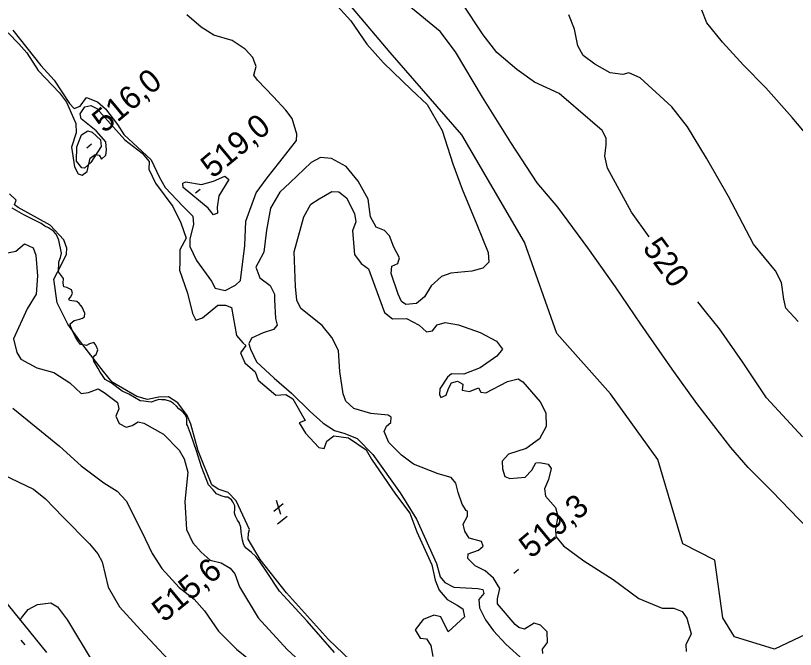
# Model space of a CAD drawing. Extents: x 347059 to 352153, y 6073752 to 6078601.
# Drawn here: x 350645.1 to 350797.1, y 6076601.8 to 6076725.3 of the extents above; entities that cross this region are included whole.
import ezdxf

# ---------------------------------------------------------------- set-up
doc = ezdxf.new("R2010")
doc.units = 0
for name, color, linetype in [('Level 1', 7, 'Continuous'), ('Level 2', 7, 'Continuous'), ('Level 21', 7, 'Continuous'), ('Level 3', 7, 'Continuous'), ('Level 4', 7, 'Continuous'), ('Level 44', 7, 'Continuous')]:
    doc.layers.add(name, color=color, linetype=linetype)

msp = doc.modelspace()

# ---------------------------------------------------------------- linework, layer by layer
at = {"layer": 'Level 1'}
for points in [[(350768.63, 6076682.21), (350765.17, 6076686.97), (350760.48, 6076695.58), (350759.98, 6076697.93), (350760.27, 6076700.13), (350760.25, 6076701.43), (350759.45, 6076702.88), (350757.14, 6076704.91), (350751.05, 6076710.13), (350746.24, 6076712.34), (350742.81, 6076714.77), (350738.91, 6076718.11), (350736.22, 6076721.55), (350732.03, 6076727.94)], [(350798.53, 6076643.18), (350791.52, 6076650.79), (350786.82, 6076657.81), (350782.34, 6076664.23), (350779.58, 6076667.6), (350778.1, 6076669.52)], [(350644.55, 6076648.8), (350653.61, 6076641.41), (350657.83, 6076637.53), (350662.25, 6076634.21), (350664.89, 6076632.58), (350666.66, 6076630.74), (350669.66, 6076624.68), (350671.7, 6076620.44), (350673.57, 6076617.51), (350676.95, 6076613.86), (350679.89, 6076611.55), (350681.9, 6076609.26)], [(350681.9, 6076609.26), (350684.61, 6076605.32), (350688.14, 6076601.79), (350691.54, 6076599.08)]]:
    msp.add_lwpolyline(points, dxfattribs=at)
at = {"layer": 'Level 2'}
for points in [[(350799.56, 6076625.36), (350792.64, 6076632.53), (350787.92, 6076637.19), (350784.57, 6076641.12), (350777.93, 6076649.72), (350773.11, 6076656.4), (350766.99, 6076665.16), (350762.08, 6076672.43), (350756.64, 6076680.04), (350750.79, 6076687.98), (350746.79, 6076692.71), (350741.66, 6076700.58), (350736.12, 6076709.43), (350730.86, 6076718.25), (350727.86, 6076722.23), (350716.34, 6076731.68)], [(350705.26, 6076730.04), (350710.47, 6076724.31), (350713.56, 6076719.74), (350716.8, 6076716.09), (350722.27, 6076710.85), (350725.3, 6076707.95), (350728.27, 6076702.88), (350730.31, 6076696.39), (350732.14, 6076691.44), (350735, 6076684.58), (350737.22, 6076679.15), (350737.33, 6076677.26), (350736.2, 6076676.08), (350734.06, 6076675.49), (350729.92, 6076675.11), (350728.13, 6076674.42), (350726.09, 6076672.6), (350724.8, 6076670.49), (350723.24, 6076669.2), (350721.2, 6076668.97), (350720.33, 6076669.56), (350719.67, 6076671), (350718.33, 6076675.03), (350718.47, 6076676.47), (350719.6, 6076677), (350719.92, 6076678.06), (350718.83, 6076680.19), (350717.96, 6076682.37), (350716.98, 6076683.41), (350715.39, 6076684.07), (350714.28, 6076686.06), (350713.82, 6076689.51), (350711.86, 6076693.03), (350709.54, 6076695.86), (350706.67, 6076697.45), (350704.53, 6076697.66), (350702.71, 6076696.68), (350698.59, 6076692.76)], [(350681.26, 6076723.04), (350678.48, 6076725.48)], [(350797.66, 6076665.68), (350795.26, 6076668.29), (350794.86, 6076670.05), (350794.45, 6076673.26), (350793.23, 6076675.54), (350788.94, 6076680.78), (350784.11, 6076690.03), (350779.81, 6076697.51), (350776.11, 6076703.63), (350773.05, 6076707.53), (350766.86, 6076713.18), (350764.66, 6076714.12), (350763.49, 6076713.8), (350761.01, 6076714.12), (350758.03, 6076715.86), (350755.76, 6076717.52), (350754.72, 6076719.42), (350754.03, 6076722.66), (350752.93, 6076725.42)], [(350799.66, 6076701.74), (350796.51, 6076705.43), (350791.36, 6076711.25), (350786.99, 6076715.63), (350782.92, 6076720.13), (350779.85, 6076723.88), (350778.88, 6076726.35)], [(350644.55, 6076722.44), (350650.01, 6076715.6), (350652.62, 6076712.74), (350655.57, 6076708.18), (350656.48, 6076707.22), (350657.68, 6076707.68), (350658.92, 6076709.36), (350661.07, 6076708.5), (350662.59, 6076707.11), (350664.97, 6076704.06), (350666.15, 6076702.13), (350671.51, 6076697.19), (350673.06, 6076693.85), (350674.23, 6076691.78), (350677.7, 6076688.19), (350679.6, 6076686.19), (350679.73, 6076684.58), (350679.03, 6076681.76), (350679.03, 6076680.32), (350680.35, 6076677.58), (350683.28, 6076673.53), (350684.01, 6076672.16), (350685.91, 6076671.75), (350687.96, 6076672.78), (350688.91, 6076673.69), (350689.78, 6076680.48), (350689.94, 6076685.23), (350691.99, 6076690.74), (350694.14, 6076693.71), (350696.6, 6076696.79), (350699.88, 6076700.94), (350699.92, 6076702.17), (350698.99, 6076705.22), (350697.78, 6076706.86), (350695.37, 6076709.49), (350692.22, 6076712.69), (350691.53, 6076713.7), (350691.98, 6076715.39), (350691.35, 6076717.12), (350689.86, 6076718.78), (350687.28, 6076720.48), (350683.71, 6076721.49), (350681.26, 6076723.04)], [(350657.93, 6076702.08), (350659.16, 6076702.83), (350660, 6076702.6), (350661.65, 6076701.06), (350661.75, 6076699.82), (350659.72, 6076696.7), (350658.53, 6076695.59), (350657.96, 6076695.65), (350656.93, 6076696.91), (350656.99, 6076699.72), (350657.93, 6076702.08)], [(350681.31, 6076692.38), (350683.67, 6076693.01), (350685.85, 6076694.02), (350686.65, 6076693.36), (350684.69, 6076690.16), (350684.4, 6076687.95), (350684.44, 6076686.79), (350683.68, 6076686.44), (350682.59, 6076687.77), (350677.73, 6076691.79), (350677.67, 6076692.67), (350678.26, 6076692.89), (350681.31, 6076692.38)], [(350698.59, 6076692.76), (350696.6, 6076690.86), (350694.8, 6076687.78), (350694.02, 6076683.45), (350693.47, 6076679.17), (350692.4, 6076677.11), (350691.89, 6076676.29), (350692.7, 6076674.19), (350694.72, 6076672.68), (350695.56, 6076671.01), (350695.53, 6076669.93), (350695.76, 6076666.29), (350696.06, 6076664.96), (350695.33, 6076664.09), (350693.33, 6076663.49), (350691.07, 6076662.42), (350690.53, 6076661.31), (350690.86, 6076660.27), (350692.07, 6076657.84), (350695.5, 6076654.6), (350698.9, 6076651.74), (350702.51, 6076648.12), (350705.02, 6076645.85), (350707.26, 6076644.4), (350709.29, 6076643.84), (350711.65, 6076642.88), (350714.73, 6076639.75), (350720.06, 6076632.28), (350723.24, 6076627.13), (350727.16, 6076618.5), (350727.84, 6076615.9), (350728.75, 6076614.8), (350730.53, 6076613.9), (350735.18, 6076613.65), (350736.17, 6076613.41), (350736.39, 6076612.67), (350735.41, 6076611.46), (350735.54, 6076609.86), (350736.68, 6076607.5), (350738.28, 6076605.4), (350740.69, 6076602.77), (350744.13, 6076599.68)], [(350704.25, 6076689.59), (350706.76, 6076691), (350708.12, 6076690.93), (350709.59, 6076689.78), (350711.17, 6076686.73), (350711.44, 6076685.12), (350710.77, 6076683.38), (350711.19, 6076678.72), (350712.46, 6076677), (350713.87, 6076675.93), (350715.87, 6076670.6), (350717.01, 6076667.46), (350718.54, 6076666.22), (350721.27, 6076666.24), (350723.74, 6076664.99), (350725.19, 6076663.69), (350726.36, 6076663.86), (350727.26, 6076665), (350728.81, 6076665.49), (350731.43, 6076665.02), (350735.66, 6076663.51), (350738.88, 6076661.82), (350740.02, 6076660.26), (350738.89, 6076658.93), (350735.65, 6076656.66), (350732.51, 6076655.38), (350730.08, 6076655.48), (350729.3, 6076654.83), (350727.79, 6076652.53), (350727.76, 6076651.45), (350727.99, 6076650.85), (350729.04, 6076651.32), (350729.52, 6076652.65), (350730.06, 6076653.75), (350731.24, 6076654.07), (350732.26, 6076653.46), (350732.15, 6076652.31), (350733.56, 6076652.03), (350735.35, 6076652.72), (350735.77, 6076651.88), (350736.77, 6076651.78), (350741, 6076653.96), (350743.06, 6076654.48), (350744.01, 6076653.95), (350747.37, 6076650.01), (350748.46, 6076647.88), (350748.56, 6076645.2), (350747.25, 6076642.81), (350744.63, 6076640.9), (350741.22, 6076639.8), (350739.94, 6076638.48), (350740.01, 6076636.96), (350740.45, 6076635.47), (350741.42, 6076635.09), (350744.46, 6076635.36), (350745.73, 6076636.68), (350746.52, 6076638.12), (350747.24, 6076638.19), (350748.94, 6076637.88), (350749.5, 6076637.03), (350749.01, 6076634.91), (350748.19, 6076633.04), (350748.41, 6076631.65), (350750.35, 6076629.44), (350750.84, 6076627.73)], [(350739.5, 6076613.62), (350738.26, 6076615.62), (350736.67, 6076617.08), (350734.68, 6076618.07), (350733.24, 6076619.51), (350733.32, 6076620.37), (350735.34, 6076621.11), (350736.27, 6076621.88), (350735.93, 6076622.78), (350733.55, 6076623.45), (350732.68, 6076624.84), (350732.37, 6076626.17), (350733.17, 6076627.75), (350733.19, 6076628.68), (350732.92, 6076628.85), (350732.17, 6076630.08), (350731.38, 6076632.33), (350730.91, 6076634.18), (350730.01, 6076635.28), (350727.49, 6076635.96), (350722.65, 6076637.88), (350720.3, 6076639.63), (350717.88, 6076642.11), (350716.93, 6076644.23), (350717.39, 6076645.26), (350718.25, 6076645.97), (350718.28, 6076647.05), (350717.74, 6076647.39), (350714.32, 6076647.73), (350711.04, 6076648.71), (350709.45, 6076650.16), (350708.94, 6076651.59), (350708.28, 6076655.91), (350708.03, 6076660.05), (350706.76, 6076662.56), (350704.83, 6076664.92), (350700.69, 6076668.21), (350699.91, 6076669.81), (350699.67, 6076672.5), (350699.38, 6076679.24), (350701.26, 6076686.06), (350702.64, 6076688.52), (350704.25, 6076689.59)], [(350663.68, 6076653.71), (350662.51, 6076654.39), (350661.86, 6076655.34), (350661.53, 6076655.82), (350661.18, 6076656.51), (350660.33, 6076657.97), (350660.22, 6076658.63), (350660.59, 6076659.09), (350660.76, 6076659.24), (350661.13, 6076660.15), (350660.79, 6076660.91), (350660.64, 6076661.17), (350660.31, 6076661.57), (350659.51, 6076661.35), (350658.91, 6076660.99), (350658.63, 6076661.06), (350657.74, 6076661.22), (350657.33, 6076661.7), (350656.76, 6076662.65), (350656.23, 6076663.64), (350655.86, 6076664.61), (350655.71, 6076665.24), (350656.46, 6076665.87), (350657.51, 6076666.14), (350658.1, 6076666.34), (350658.49, 6076666.59), (350658.56, 6076667.32), (350658.04, 6076668.47), (350657.82, 6076668.81), (350657.49, 6076669.21), (350657.03, 6076669.57), (350655.57, 6076669.78), (350655.47, 6076670), (350655.84, 6076670.46), (350656.19, 6076671.2), (350655.96, 6076671.83), (350655.05, 6076672.28), (350654.45, 6076672.46), (350654.35, 6076673.12), (350654.43, 6076674.09), (350654.02, 6076674.58), (350653.44, 6076675.36), (350653.48, 6076677.28), (350653.8, 6076678.15), (350654, 6076678.99), (350653.52, 6076681.53), (350653.18, 6076682.29), (350652.93, 6076682.76), (350652.48, 6076683.29), (350652.1, 6076683.57), (350651.48, 6076683.95), (350650.77, 6076684.26), (350650.03, 6076684.77), (350646.7, 6076686.49), (350644.4, 6076687.8)], [(350642.83, 6076678.95), (350645.1, 6076679.37), (350646.82, 6076680.79), (350648.48, 6076680.05), (350648.99, 6076678.62), (350649.32, 6076674.55), (350649.05, 6076671.03), (350647.34, 6076668.17), (350644.68, 6076662.3), (350645.29, 6076659.64), (350646.1, 6076658.33), (350649.18, 6076656.65), (350652.54, 6076655.74), (350655.66, 6076653.7), (350657.83, 6076651.67), (350659.29, 6076651.82), (350661.16, 6076652.57)], [(350707.29, 6076601.15), (350701.9, 6076607.26), (350696.56, 6076613.14), (350693.97, 6076616.93), (350692.63, 6076618.97), (350691.89, 6076619.86), (350691.06, 6076620.66), (350690.06, 6076621.49), (350689.73, 6076621.88), (350689.52, 6076622.31), (350689.29, 6076623.03), (350689.07, 6076624.64), (350689.02, 6076625.58), (350688.65, 6076626.47), (350688.32, 6076626.95), (350687.94, 6076627.76), (350687.81, 6076628.1), (350687.78, 6076628.31), (350687.82, 6076629.16), (350687.79, 6076629.74), (350687.4, 6076630.55), (350687.19, 6076630.89), (350686.46, 6076631.41), (350685.97, 6076631.45), (350685.17, 6076631.68), (350684.22, 6076632.09), (350683.59, 6076632.84), (350682.69, 6076633.82), (350681.31, 6076637.33), (350680.42, 6076640.27), (350679.17, 6076643.82), (350678.57, 6076645.42), (350678.47, 6076645.63), (350678.48, 6076646.25), (350678.48, 6076646.7), (350678.39, 6076647.07), (350678.22, 6076647.45), (350677.39, 6076648.26), (350676.89, 6076648.67), (350676.44, 6076649.2), (350675.87, 6076649.7), (350675.25, 6076650.08), (350674.21, 6076650.42), (350673.52, 6076650.44), (350672.99, 6076650.45), (350672.02, 6076650.16), (350671.59, 6076649.95), (350670.99, 6076650.05), (350670.09, 6076650.13), (350669.36, 6076650.19), (350667.14, 6076651.49), (350665.88, 6076652.09), (350663.68, 6076653.71)], [(350661.16, 6076652.57), (350662.31, 6076651.81), (350664.93, 6076649.89), (350665.17, 6076648.64), (350664.6, 6076647.25), (350665.25, 6076645.81), (350666.62, 6076645.1), (350667.81, 6076645.41), (350668.95, 6076646.1), (350670.08, 6076645.84), (350673.9, 6076643.73), (350676.98, 6076640.61), (350677.97, 6076638.92), (350678.65, 6076636.32), (350678.1, 6076630.6), (350678.37, 6076625.16), (350679.63, 6076622.51), (350681.25, 6076620.69), (350683.04, 6076619.14), (350685.15, 6076618.64), (350686.92, 6076617.6), (350687.82, 6076616.5), (350688.73, 6076613.95), (350692.39, 6076607.89), (350698.05, 6076601.77), (350701.29, 6076598.77)], [(350639.37, 6076637.35), (350648.56, 6076632.99), (350650.89, 6076631.1), (350654.28, 6076627.59), (350659.51, 6076622.32), (350661.11, 6076620.37), (350661.97, 6076618.84)], [(350750.84, 6076627.73), (350750.38, 6076625.25), (350750.39, 6076623.8), (350751.93, 6076621.92), (350755.89, 6076619), (350761.58, 6076615.41), (350766.6, 6076611.66), (350771.16, 6076609.77), (350773.46, 6076609.83), (350775.05, 6076609.17), (350776, 6076607.85), (350776.79, 6076604.81), (350775.79, 6076602.67), (350775.81, 6076601.37)], [(350661.97, 6076618.84), (350663.15, 6076613.9), (350665.36, 6076610.08), (350669.44, 6076605.57), (350675.82, 6076598.75)], [(350747.91, 6076600.95), (350747.85, 6076601.83), (350748.77, 6076603.11), (350748.75, 6076605.2), (350747.44, 6076606.49), (350746.18, 6076606.9), (350744.28, 6076605.72), (350743.23, 6076606.04), (350742.49, 6076606.61), (350739.07, 6076610.63), (350739.03, 6076611.65), (350739.5, 6076613.62)], [(350645.96, 6076607.47), (350646.21, 6076607.91), (350647.52, 6076609.52), (350649.33, 6076610.49), (350651.94, 6076610.81), (350653.23, 6076610.04), (350655.2, 6076607.47), (350660.2, 6076599.14)]]:
    msp.add_lwpolyline(points, dxfattribs=at)
at = {"layer": 'Level 21'}
msp.add_lwpolyline([(350484.39, 6076829.01), (350493.99, 6076817.18), (350501.43, 6076807.34), (350505.97, 6076801.28), (350513.44, 6076792.21), (350519.39, 6076783.91), (350526.31, 6076773.43), (350533.24, 6076763.85), (350539.37, 6076754.43), (350548.29, 6076741.97), (350556.35, 6076730.58), (350564.41, 6076719.34), (350571.68, 6076707.82), (350580.93, 6076694.96), (350586.7, 6076685.17), (350594.4, 6076673.03), (350602.77, 6076660.71), (350609.28, 6076651.53), (350616.86, 6076641.52), (350626.76, 6076629.41), (350634.91, 6076620.15), (350642.52, 6076611.72), (350651.07, 6076601.17)], dxfattribs=at)
at = {"layer": 'Level 3'}
for p, q in [((350658.98, 6076699.55), (350659.9, 6076700.32)), ((350680.16, 6076690.73), (350681.08, 6076691.5)), ((350695.89, 6076630.87), (350696.72, 6076628.12)), ((350695.43, 6076628.74), (350697.24, 6076630.23)), ((350696.15, 6076626.22), (350698, 6076627.75)), ((350742.22, 6076616.63), (350743.14, 6076617.4)), ((350646.95, 6076602.66), (350646.18, 6076603.58))]:
    msp.add_line(p, q, dxfattribs=at)
at = {"layer": 'Level 4'}
for points in [[(350643.6, 6076721.94), (350645.73, 6076719.81), (350647.24, 6076718.07), (350649.49, 6076714.62), (350653.61, 6076710.25), (350654.99, 6076708.4), (350656.84, 6076704.25), (350656.91, 6076702.44), (350655.99, 6076699.67), (350656.55, 6076695.81), (350657.28, 6076694.47), (350658.04, 6076694.19), (350659.01, 6076694.91), (350659.63, 6076697.51), (350660.56, 6076698.2), (350661.37, 6076698.12), (350661.79, 6076697.34), (350662.68, 6076698.07), (350662.82, 6076699.08), (350662.69, 6076700.69), (350660.76, 6076702.84), (350657.87, 6076705.17), (350657.64, 6076706.17), (350658.6, 6076707.55), (350659.73, 6076707.81), (350660.9, 6076707.2), (350663.04, 6076704.78), (350666.38, 6076701.1), (350669.77, 6076698.52), (350671.13, 6076696.87), (350671.03, 6076695.37), (350672.36, 6076692.66), (350675.73, 6076688.12), (350677.31, 6076684.94), (350678.33, 6076681.89)], [(350651.8, 6076684.45), (350645.58, 6076687.93), (350644.85, 6076688.45), (350645.18, 6076689.32), (350643.91, 6076690.59)], [(350710.36, 6076599.6), (350706.08, 6076603.71), (350704.34, 6076605.64), (350697.9, 6076612.82), (350692.79, 6076619.3), (350690.43, 6076623.26), (350690.46, 6076624.4), (350690.65, 6076625.16), (350688.08, 6076630.73), (350686.51, 6076632.36), (350684.56, 6076633), (350683.34, 6076633.86), (350680.7, 6076640.5), (350679.23, 6076645.64), (350678.54, 6076647.38), (350676.73, 6076649.85), (350674.91, 6076650.97), (350673.02, 6076650.91), (350670.76, 6076650.48), (350668.72, 6076651.05), (350663.87, 6076653.86), (350662.18, 6076655.9), (350657.75, 6076661.74), (350655.25, 6076665.14), (350653.16, 6076669.31), (350652.5, 6076673.91), (350653.95, 6076676.68), (350655.02, 6076678.82), (350655.05, 6076679.96), (350654.47, 6076681.57), (350651.8, 6076684.45)], [(350678.33, 6076681.89), (350677.12, 6076679.64), (350677.1, 6076677.31), (350677.03, 6076675.68), (350678.56, 6076671.19), (350679.57, 6076667.25), (350680.22, 6076665.92), (350681.49, 6076666.36), (350684.52, 6076668.85), (350686, 6076668.87), (350687.14, 6076668.39), (350688.17, 6076662.97), (350689.39, 6076661.5), (350689.95, 6076660.99), (350688.91, 6076659.54), (350689.79, 6076657.65), (350691.79, 6076655.86), (350692.37, 6076654.25), (350695.82, 6076651.33), (350697.8, 6076651.46), (350699.11, 6076650.6), (350701.54, 6076646.39), (350700.34, 6076645.94), (350701.58, 6076643.89), (350704.22, 6076641.13), (350705.27, 6076640.95), (350705.78, 6076642.33), (350707.15, 6076643.38), (350710.02, 6076642.98), (350713.45, 6076640.64), (350714.46, 6076638.86), (350719.13, 6076632.02), (350721.97, 6076628.3), (350723.3, 6076624.69), (350726.21, 6076618.26), (350726.9, 6076615.25), (350727.66, 6076613.33), (350729.24, 6076611.5), (350731.15, 6076610.37), (350732.31, 6076609.68), (350732.61, 6076608.14), (350729.41, 6076605.22), (350728.01, 6076608.1), (350726.61, 6076608.44), (350724.56, 6076607.58), (350723.01, 6076605.56), (350723.96, 6076603.96), (350725.18, 6076603.84), (350726.03, 6076602.52), (350726.44, 6076600.4)]]:
    msp.add_lwpolyline(points, dxfattribs=at)
at = {"layer": 'Level 44'}
msp.add_lwpolyline([(350802.81, 6076606.41), (350793.09, 6076601.78), (350785.25, 6076604.2), (350782.96, 6076607.91), (350781.42, 6076619.13), (350775.19, 6076622.35), (350770.31, 6076638.75), (350761.08, 6076651.57), (350750.61, 6076663.37), (350744.31, 6076681.13), (350732.11, 6076702.07), (350718.12, 6076718.13), (350693.48, 6076747.29), (350664.22, 6076767.61), (350653.34, 6076763.45), (350650.85, 6076756.35), (350661.75, 6076748.92), (350677.48, 6076737.43), (350678.14, 6076732.46), (350668.27, 6076729.43), (350663.45, 6076730.39), (350657.13, 6076735.17), (350642.52, 6076750.72)], dxfattribs=at)

# ---------------------------------------------------------------- texts
at = {"layer": 'Level 1'}
msp.add_text('520', height=4.5, rotation=306.6396, dxfattribs=at).set_placement((350767.2, 6076679.97))
at = {"layer": 'Level 3'}
for s, rotation, p in [('516,0', 39.62, (350662.34, 6076702.26)), ('519,0', 39.62, (350683.52, 6076693.44)), ('519,3', 39.62, (350745.58, 6076619.34)), ('  515,6', 39.57, (350671.42, 6076604.77))]:
    msp.add_text(s, height=4.5, rotation=rotation, dxfattribs=at).set_placement(p)

doc.saveas('drawing.dxf')
